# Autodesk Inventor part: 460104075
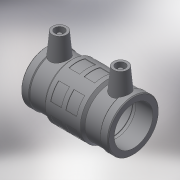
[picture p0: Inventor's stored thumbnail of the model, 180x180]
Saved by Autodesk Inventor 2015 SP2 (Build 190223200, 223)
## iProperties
Created: 2017-06
Part Number: 460104075
Material: Generic
Description: PLASSON LIGHTFIT COUPLER 75
Document SubType Name: Modeling
Designer: KIM
Mass: 89.5427 g
Surface Area: 304.58 cm^2
Volume: 89.5427 cm^3
Density: 1 g/cm^3
Appearance: Default
Author: KIM
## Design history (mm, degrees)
derived "460104.ipt"
feature "Solid1::460104.ipt"
tag "TaggingFeature1"
body "Solid1"
other parameters: "d13" = 126, "d14" = 17.6296, "d15" = 61, "d16" = 61, "d17" = 74.25, "d18" = 75, "d19" = 3.52592, "d20" = 168 deg, "d22" = 84.6, "d24" = 82.062, "d25" = 135 deg, "d26" = 50.4, "d27" = 135 deg, "d29" = 63, "d35" = 15, "d39" = 5 deg, "d44" = 4, "d46" = 14, "d47" = 0, "d52" = 88.2, "d53" = 6.3, "d54" = 6.3, "d55" = 6.3, "d56" = 35 deg, "d58" = 360 deg, "d60" = 12.2, "d61" = 135 deg, "d62" = 50.4, "d63" = 3, "d64" = 0, "d_" = 75, "L_" = 126, "L_1" = 61, "A_" = 63, "d_2" = 8
